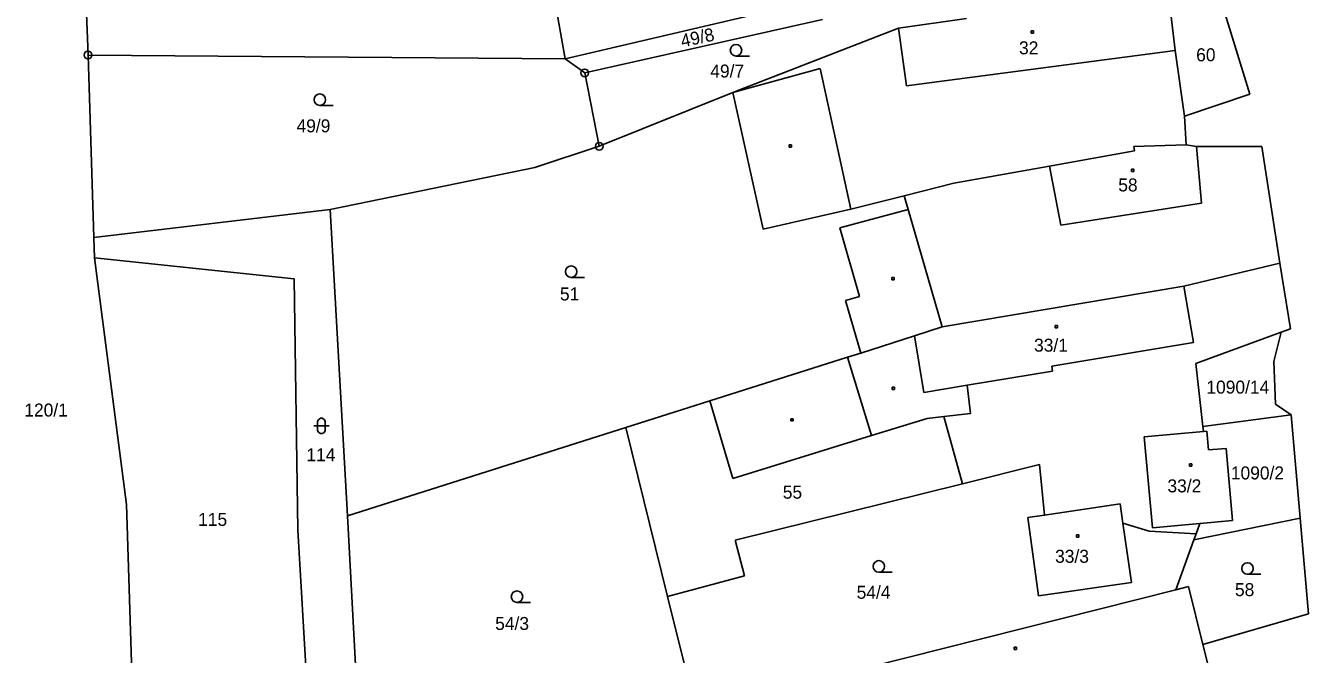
# Model space of a CAD drawing. Extents: x -794142 to -791199, y -1109267 to -1105626.
# Drawn here: x -793648.7 to -793481, y -1107828.1 to -1107745.8 of the extents above; entities that cross this region are included whole.
import ezdxf

# ---------------------------------------------------------------- set-up
doc = ezdxf.new("R2010")
doc.units = 0
for name, color, linetype in [('Vrstva 1', 7, 'Continuous'), ('Vrstva 14', 7, 'Continuous'), ('Vrstva 15', 7, 'Continuous'), ('Vrstva 2', 7, 'Continuous'), ('Vrstva 23', 7, 'Continuous'), ('Vrstva 25', 7, 'Continuous'), ('Vrstva 28', 7, 'Continuous')]:
    doc.layers.add(name, color=color, linetype=linetype)

msp = doc.modelspace()

# ---------------------------------------------------------------- linework, layer by layer
at = {"layer": 'Vrstva 1'}
for p, q in [((-793582.41, -1107726.59), (-793578.15, -1107750.15)), ((-793640.56, -1107749.63), (-793641.17, -1107732.89)), ((-793499.36, -1107741.17), (-793498.42, -1107749.05)), ((-793493.09, -1107740.25), (-793488.64, -1107754.77)), ((-793578.15, -1107750.15), (-793544.63, -1107742.22)), ((-793575.62, -1107751.97), (-793544.54, -1107744.97)), ((-793534.59, -1107746.1), (-793525.71, -1107744.85)), ((-793534.59, -1107746.1), (-793556.26, -1107754.55)), ((-793578.15, -1107750.15), (-793640.56, -1107749.63)), ((-793639.81, -1107773.49), (-793640.56, -1107749.63)), ((-793498.42, -1107749.05), (-793497.19, -1107757.62)), ((-793578.15, -1107750.15), (-793575.62, -1107751.97)), ((-793575.62, -1107751.97), (-793573.72, -1107761.58)), ((-793556.26, -1107754.55), (-793573.72, -1107761.58)), ((-793556.26, -1107754.55), (-793552.28, -1107772.44)), ((-793488.64, -1107754.77), (-793497.19, -1107757.62)), ((-793497.19, -1107757.62), (-793496.97, -1107761.37)), ((-793573.72, -1107761.58), (-793582.14, -1107764.33)), ((-793503.82, -1107761.59), (-793496.97, -1107761.37)), ((-793503.73, -1107762.15), (-793503.82, -1107761.59)), ((-793496.97, -1107761.37), (-793495.64, -1107761.62)), ((-793495.64, -1107761.62), (-793487.07, -1107761.62)), ((-793484.73, -1107776.88), (-793487.07, -1107761.62)), ((-793503.73, -1107762.15), (-793514.86, -1107764.16)), ((-793608.89, -1107769.83), (-793582.14, -1107764.33)), ((-793514.86, -1107764.16), (-793527.36, -1107766.42)), ((-793533.83, -1107768.05), (-793527.36, -1107766.42)), ((-793540.84, -1107769.81), (-793533.83, -1107768.05)), ((-793533.31, -1107769.86), (-793533.83, -1107768.05)), ((-793639.81, -1107773.49), (-793608.89, -1107769.83)), ((-793608.89, -1107769.83), (-793606.65, -1107809.95)), ((-793552.28, -1107772.44), (-793540.84, -1107769.81)), ((-793533.31, -1107769.86), (-793542.25, -1107772.25)), ((-793639.81, -1107773.49), (-793639.7, -1107776.19)), ((-793542.25, -1107772.25), (-793539.67, -1107781.24)), ((-793639.7, -1107776.19), (-793613.59, -1107778.94)), ((-793639.7, -1107776.19), (-793635.53, -1107808.45)), ((-793497.26, -1107779.86), (-793484.73, -1107776.88)), ((-793484.73, -1107776.88), (-793483.34, -1107785.48)), ((-793613.59, -1107778.94), (-793613.14, -1107811.81)), ((-793528.87, -1107785.2), (-793497.26, -1107779.86)), ((-793539.67, -1107781.24), (-793541.51, -1107781.77)), ((-793541.51, -1107781.77), (-793539.5, -1107788.63)), ((-793532.49, -1107786.4), (-793528.87, -1107785.2)), ((-793539.5, -1107788.63), (-793532.49, -1107786.4)), ((-793484.54, -1107785.92), (-793495.71, -1107789.98)), ((-793484.54, -1107785.92), (-793485.53, -1107789.73)), ((-793483.34, -1107785.48), (-793484.54, -1107785.92)), ((-793541.27, -1107789.19), (-793539.5, -1107788.63)), ((-793559.24, -1107794.9), (-793541.27, -1107789.19)), ((-793495.71, -1107789.98), (-793494.8, -1107798.25)), ((-793485.53, -1107789.73), (-793485.31, -1107795.3)), ((-793570.23, -1107798.39), (-793559.24, -1107794.9)), ((-793556.24, -1107805.03), (-793559.24, -1107794.9)), ((-793485.31, -1107795.3), (-793483.26, -1107796.73)), ((-793530.86, -1107797.19), (-793528.64, -1107796.93)), ((-793528.64, -1107796.93), (-793526.23, -1107805.73)), ((-793483.26, -1107796.73), (-793494.8, -1107798.25)), ((-793482.09, -1107810.22), (-793483.26, -1107796.73)), ((-793606.65, -1107809.95), (-793570.23, -1107798.39)), ((-793570.23, -1107798.39), (-793564.77, -1107820.47)), ((-793538.11, -1107799.41), (-793530.86, -1107797.19)), ((-793494.8, -1107798.25), (-793494.73, -1107798.91)), ((-793556.24, -1107805.03), (-793538.11, -1107799.41)), ((-793494.73, -1107798.91), (-793502.47, -1107799.61)), ((-793502.47, -1107799.61), (-793501.39, -1107811.51)), ((-793494.27, -1107798.87), (-793494.73, -1107798.91)), ((-793494.05, -1107801.29), (-793494.27, -1107798.87)), ((-793491.74, -1107801.13), (-793494.05, -1107801.29)), ((-793491.74, -1107801.13), (-793490.91, -1107810.56)), ((-793526.23, -1107805.73), (-793516.16, -1107803.23)), ((-793516.16, -1107803.23), (-793515.48, -1107809.83)), ((-793555.95, -1107813.13), (-793526.23, -1107805.73)), ((-793635.53, -1107808.45), (-793634.1, -1107853.25)), ((-793515.48, -1107809.83), (-793505.61, -1107808.36)), ((-793505.61, -1107808.36), (-793505.25, -1107810.89)), ((-793604.64, -1107847.08), (-793606.65, -1107809.95)), ((-793517.68, -1107810.16), (-793515.48, -1107809.83)), ((-793516.29, -1107820.41), (-793517.68, -1107810.16)), ((-793495.96, -1107813.09), (-793482.09, -1107810.22)), ((-793481, -1107822.76), (-793482.09, -1107810.22)), ((-793610.84, -1107849.94), (-793613.14, -1107811.81)), ((-793505.25, -1107810.89), (-793504.14, -1107818.65)), ((-793505.25, -1107810.89), (-793501.81, -1107811.94)), ((-793501.81, -1107811.94), (-793495.67, -1107812.29)), ((-793501.39, -1107811.51), (-793495.19, -1107810.95)), ((-793495.67, -1107812.29), (-793495.19, -1107810.95)), ((-793495.19, -1107810.95), (-793490.91, -1107810.56)), ((-793554.74, -1107817.79), (-793555.95, -1107813.13)), ((-793498.31, -1107819.6), (-793495.96, -1107813.09)), ((-793495.96, -1107813.09), (-793495.67, -1107812.29)), ((-793564.77, -1107820.47), (-793554.74, -1107817.79)), ((-793516.29, -1107820.41), (-793504.14, -1107818.65)), ((-793564.77, -1107820.47), (-793560.8, -1107836.53)), ((-793498.31, -1107819.6), (-793543.6, -1107831.04)), ((-793496.65, -1107819.18), (-793498.31, -1107819.6)), ((-793496.65, -1107819.18), (-793494.79, -1107826.79)), ((-793494.79, -1107826.79), (-793481, -1107822.76)), ((-793494.79, -1107826.79), (-793494.12, -1107829.52))]:
    msp.add_line(p, q, dxfattribs=at)
at = {"layer": 'Vrstva 2'}
for p, q in [((-793533.56, -1107753.67), (-793534.59, -1107746.1)), ((-793498.42, -1107749.05), (-793533.56, -1107753.67)), ((-793556.26, -1107754.55), (-793544.84, -1107751.39)), ((-793544.84, -1107751.39), (-793540.84, -1107769.81)), ((-793495.64, -1107761.62), (-793494.97, -1107769)), ((-793514.86, -1107764.16), (-793513.35, -1107771.88)), ((-793528.87, -1107785.2), (-793533.31, -1107769.86)), ((-793513.35, -1107771.88), (-793494.97, -1107769)), ((-793497.26, -1107779.86), (-793496.02, -1107787.25)), ((-793532.49, -1107786.4), (-793531.26, -1107793.79)), ((-793514.56, -1107790.33), (-793496.02, -1107787.25)), ((-793538.11, -1107799.41), (-793541.27, -1107789.19)), ((-793514.56, -1107790.33), (-793514.45, -1107791)), ((-793514.45, -1107791), (-793525.59, -1107792.85)), ((-793525.59, -1107792.85), (-793531.26, -1107793.79)), ((-793525.16, -1107796.53), (-793525.59, -1107792.85)), ((-793528.64, -1107796.93), (-793525.16, -1107796.53))]:
    msp.add_line(p, q, dxfattribs=at)
at = {"layer": 'Vrstva 23'}
for p, q in [((-793555.83, -1107749.76), (-793554.08, -1107749.76)), ((-793610.25, -1107756.23), (-793608.5, -1107756.23)), ((-793577.39, -1107778.73), (-793575.64, -1107778.73)), ((-793611.04, -1107798.17), (-793609.04, -1107798.17)), ((-793610.54, -1107797.57), (-793610.44, -1107797.37)), ((-793610.54, -1107798.77), (-793610.54, -1107797.57)), ((-793610.44, -1107797.37), (-793610.34, -1107797.27)), ((-793610.34, -1107797.27), (-793610.14, -1107797.17)), ((-793610.14, -1107797.17), (-793609.94, -1107797.17)), ((-793609.94, -1107797.17), (-793609.74, -1107797.27)), ((-793609.74, -1107797.27), (-793609.64, -1107797.37)), ((-793609.64, -1107797.37), (-793609.54, -1107797.57)), ((-793609.54, -1107797.57), (-793609.54, -1107798.77)), ((-793610.44, -1107798.97), (-793610.54, -1107798.77)), ((-793610.34, -1107799.07), (-793610.44, -1107798.97)), ((-793610.14, -1107799.17), (-793610.34, -1107799.07)), ((-793609.94, -1107799.17), (-793610.14, -1107799.17)), ((-793609.74, -1107799.07), (-793609.94, -1107799.17)), ((-793609.64, -1107798.97), (-793609.74, -1107799.07)), ((-793609.54, -1107798.77), (-793609.64, -1107798.97)), ((-793537.16, -1107817.3), (-793535.41, -1107817.3)), ((-793488.96, -1107817.58), (-793487.21, -1107817.58)), ((-793584.47, -1107821.26), (-793582.72, -1107821.26))]:
    msp.add_line(p, q, dxfattribs=at)
for centre in [(-793555.83, -1107749.01), (-793610.25, -1107755.48), (-793577.39, -1107777.98), (-793537.16, -1107816.55), (-793488.96, -1107816.83), (-793584.47, -1107820.51)]:
    msp.add_circle(centre, 0.75, dxfattribs=at)
at = {"layer": 'Vrstva 25'}
for p, q in [((-793517.25, -1107746.48), (-793516.95, -1107746.48)), ((-793517.25, -1107746.78), (-793517.25, -1107746.48)), ((-793516.95, -1107746.48), (-793516.95, -1107746.78)), ((-793516.95, -1107746.78), (-793517.25, -1107746.78)), ((-793548.88, -1107761.4), (-793548.58, -1107761.4)), ((-793548.88, -1107761.7), (-793548.88, -1107761.4)), ((-793548.58, -1107761.7), (-793548.88, -1107761.7)), ((-793548.58, -1107761.4), (-793548.58, -1107761.7)), ((-793504.13, -1107764.56), (-793503.83, -1107764.56)), ((-793504.13, -1107764.86), (-793504.13, -1107764.56)), ((-793503.83, -1107764.86), (-793504.13, -1107764.86)), ((-793503.83, -1107764.56), (-793503.83, -1107764.86)), ((-793535.46, -1107778.75), (-793535.16, -1107778.75)), ((-793535.46, -1107779.05), (-793535.46, -1107778.75)), ((-793535.16, -1107779.05), (-793535.46, -1107779.05)), ((-793535.16, -1107778.75), (-793535.16, -1107779.05)), ((-793514.09, -1107785.01), (-793513.79, -1107785.01)), ((-793514.09, -1107785.31), (-793514.09, -1107785.01)), ((-793513.79, -1107785.31), (-793514.09, -1107785.31)), ((-793513.79, -1107785.01), (-793513.79, -1107785.31)), ((-793535.42, -1107793.11), (-793535.12, -1107793.11)), ((-793535.42, -1107793.41), (-793535.42, -1107793.11)), ((-793535.12, -1107793.41), (-793535.42, -1107793.41)), ((-793535.12, -1107793.11), (-793535.12, -1107793.41)), ((-793548.66, -1107797.22), (-793548.36, -1107797.22)), ((-793548.66, -1107797.52), (-793548.66, -1107797.22)), ((-793548.36, -1107797.52), (-793548.66, -1107797.52)), ((-793548.36, -1107797.22), (-793548.36, -1107797.52)), ((-793496.54, -1107803.14), (-793496.24, -1107803.14)), ((-793496.54, -1107803.44), (-793496.54, -1107803.14)), ((-793496.24, -1107803.44), (-793496.54, -1107803.44)), ((-793496.24, -1107803.14), (-793496.24, -1107803.44)), ((-793511.31, -1107812.42), (-793511.01, -1107812.42)), ((-793511.31, -1107812.72), (-793511.31, -1107812.42)), ((-793511.01, -1107812.72), (-793511.31, -1107812.72)), ((-793511.01, -1107812.42), (-793511.01, -1107812.72)), ((-793519.48, -1107827.12), (-793519.18, -1107827.12)), ((-793519.48, -1107827.42), (-793519.48, -1107827.12)), ((-793519.18, -1107827.12), (-793519.18, -1107827.42)), ((-793519.18, -1107827.42), (-793519.48, -1107827.42))]:
    msp.add_line(p, q, dxfattribs=at)
at = {"layer": 'Vrstva 28'}
for centre, radius in [((-793640.56, -1107749.63), 0.5), ((-793640.56, -1107749.63), 0.01), ((-793575.62, -1107751.97), 0.5), ((-793575.62, -1107751.97), 0.01), ((-793573.72, -1107761.58), 0.5), ((-793573.72, -1107761.58), 0.01)]:
    msp.add_circle(centre, radius, dxfattribs=at)

# ---------------------------------------------------------------- texts
at = {"layer": 'Vrstva 14'}
msp.add_text('49/8', height=1.7, rotation=12.24234, dxfattribs=at).set_placement((-793562.864, -1107748.648))
for s, p in [('60', (-793495.666, -1107750.45)), ('49/7', (-793559.192, -1107752.58)), ('49/9', (-793613.296, -1107759.75)), ('51', (-793578.856, -1107781.75)), ('1090/14', (-793494.33, -1107793.94)), ('120/1', (-793648.885, -1107796.94)), ('114', (-793611.999, -1107802.78)), ('1090/2', (-793491.131, -1107805.17)), ('55', (-793549.719, -1107807.69)), ('115', (-793626.159, -1107811.25)), ('58', (-793490.593, -1107820.44)), ('54/4', (-793540.058, -1107820.79)), ('54/3', (-793587.32, -1107824.87))]:
    msp.add_text(s, height=1.7, dxfattribs=at).set_placement(p)
at = {"layer": 'Vrstva 15'}
for s, p in [('32', (-793518.827, -1107749.54)), ('58', (-793505.853, -1107767.48)), ('33/1', (-793516.863, -1107788.45)), ('33/2', (-793499.42, -1107806.86)), ('33/3', (-793514.11, -1107816.08))]:
    msp.add_text(s, height=1.7, dxfattribs=at).set_placement(p)

doc.saveas('drawing.dxf')
